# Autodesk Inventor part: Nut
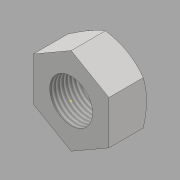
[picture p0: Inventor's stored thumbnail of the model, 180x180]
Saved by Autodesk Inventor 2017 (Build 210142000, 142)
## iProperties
Created: 2016-05
Part Number: Nut
Material: Generic
Document SubType Name: Modeling
Designer: CADCIM
Density: 1 g/cm^3
Appearance: Default
Author: CADCIM
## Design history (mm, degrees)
sketch "Sketch1"
  geometry: L1 (0, -33.255)-(-28.8, -16.628); L2 (-28.8, -16.628)-(-28.8, 16.628); L3 (-28.8, 16.628)-(0, 33.255); L4 (0, 33.255)-(28.8, 16.628); L5 (28.8, 16.628)-(28.8, -16.628); L6 (28.8, -16.628)-(0, -33.255); 2 further points
  constraints: 12 end point, 1 coincident, 13 other
  dimensions: "d0" = 57.6 distance between parallel lines of L2 L5
extrude "Extrusion1" new body sketch "Sketch1" stored distance "d1" = 28.8; taper "d2" = 0 deg
sketch "Sketch2"
  geometry: L1 (0, 33.255)-(-28.8, 16.628) reference; C1 r 28.8 at (0, 0); 1 further point
  constraints: 1 centre point, 1 coincident, 1 tangent
extrude "Extrusion2" sketch "Sketch2" distance "d3" = 28.8; taper "d4" = 60 deg
sketch "Sketch3"
  geometry: 1 further point
hole "Hole1" diameter "d7" = 32.752; stored, may be unused: countersink angle "d11" = 90 deg, drill point angle "d13" = 118 deg; dims "d5" = 10, "d6" = 10, "d8" = 72, "d9" = 4, "d10" = 2, "d12" = 85.1
body "Solid1"
